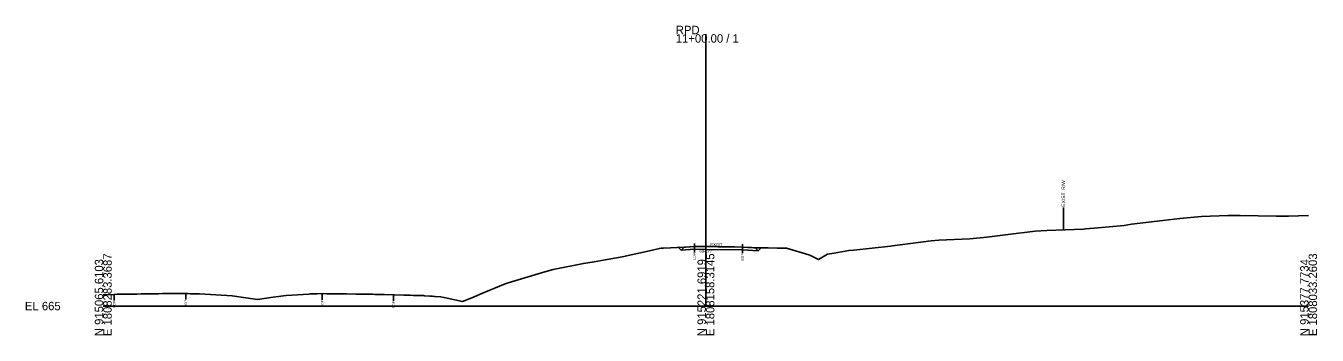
# Model space of a CAD drawing. Extents: x -26 to 403, y -10 to 8517.
# Drawn here: x -25.7 to 402.8, y 1990.3 to 2093.2 of the extents above; entities that cross this region are included whole.
import ezdxf

# ---------------------------------------------------------------- set-up
doc = ezdxf.new("R2010")
doc.units = 0
for name, color, linetype in [('Exist Cross Section Cell', 7, 'Continuous'), ('Exist XS Center Line Elevation Label', 7, 'Continuous'), ('Exist XS Ground Line', 7, 'Continuous'), ('Old_Level_10', 7, 'Continuous'), ('Prop XS Earthwork Shape', 7, 'Continuous'), ('Prop XS EOT Tick Mark', 7, 'Continuous'), ('Prop XS Finish Grade', 7, 'Continuous'), ('Prop XS Finish Grade Paved Shoulder', 7, 'Continuous'), ('Prop XS Finish Grade Pavement', 7, 'Continuous'), ('Prop XS Pvmt Edge Slope', 7, 'Continuous'), ('Prop XS SE Text', 7, 'Continuous'), ('Prop XS Subgrade Earthwork', 7, 'Continuous')]:
    doc.layers.add(name, color=color, linetype=linetype)

msp = doc.modelspace()

# ---------------------------------------------------------------- linework, layer by layer
at = {"layer": 'Exist Cross Section Cell'}
for p, q in [((200, 2000), (200, 2090.35)), ((0, 2000), (200, 2000)), ((200, 2000), (400, 2000))]:
    msp.add_line(p, q, dxfattribs=at)
at = {"layer": 'Exist XS Ground Line'}
msp.add_lwpolyline([(0, 2003.72), (0.56, 2003.73), (1.04, 2003.76), (3.65, 2003.89), (4.59, 2003.91), (6.87, 2003.94), (8.53, 2003.97), (9.38, 2003.98), (10.07, 2003.99), (11.17, 2004), (12.54, 2004.01), (12.95, 2004.01), (13.29, 2004.02), (15.55, 2004.06), (16.51, 2004.08), (18.28, 2004.1), (19.68, 2004.12), (20.49, 2004.13), (22.9, 2004.15), (23.63, 2004.16), (24.53, 2004.17), (26.1, 2004.18), (26.82, 2004.19), (27.4, 2004.2), (28.12, 2004.14), (28.97, 2004.07), (29.31, 2004.07), (31.58, 2004.07), (31.91, 2004.05), (42.81, 2003.35), (47.34, 2002.7), (51.16, 2002.17), (56.37, 2002.91), (60.68, 2003.54), (68.2, 2003.99), (68.7, 2004.02), (69, 2004.02), (70.15, 2004.04), (70.95, 2004.05), (72.68, 2004.12), (74.17, 2004.09), (75.19, 2004.08), (76.5, 2004.07), (76.98, 2004.06), (77.35, 2004.06), (80.74, 2004.03), (83.79, 2003.99), (84.19, 2003.99), (84.74, 2003.98), (86.95, 2003.94), (88.5, 2003.91), (89.42, 2003.9), (90.15, 2003.89), (92.52, 2003.85), (92.98, 2003.84), (93.35, 2003.83), (96.35, 2003.78), (96.68, 2003.77), (99.76, 2003.63), (100.53, 2003.61), (101.86, 2003.57), (102.95, 2003.55), (104.52, 2003.51), (105.58, 2003.49), (106.3, 2003.47), (106.63, 2003.44), (108.38, 2003.31), (109.26, 2003.24), (109.79, 2003.2), (110.14, 2003.18), (111.92, 2003.07), (113.18, 2002.8), (119.23, 2001.47), (122.29, 2002.74), (126.46, 2004.53), (133.33, 2007.36), (133.76, 2007.52), (135.5, 2008.04), (146.58, 2011.42), (149.33, 2012.12), (159.39, 2014.15), (162.87, 2014.71), (165.32, 2015.14), (172.2, 2016.41), (181.31, 2018.39), (184.58, 2019.16), (185.18, 2019.19), (185.87, 2019.22), (192.81, 2019.58), (193.3, 2019.6), (196.17, 2019.81), (197.11, 2019.8), (197.92, 2019.79), (199.09, 2019.78), (200, 2019.77), (200.44, 2019.76), (202.29, 2019.74), (203.4, 2019.74), (203.91, 2019.73), (204.3, 2019.73), (205.48, 2019.71), (206.79, 2019.68), (208.69, 2019.65), (209.63, 2019.64), (212.12, 2019.6), (212.5, 2019.57), (213.92, 2019.47), (215.1, 2019.41), (215.9, 2019.38), (216.36, 2019.37), (220.7, 2019.32), (223.65, 2019.28), (224.68, 2019.27), (226.79, 2019.25), (234.1, 2016.97), (234.7, 2016.77), (237.41, 2015.46), (240.32, 2017.25), (242.5, 2017.63), (247.4, 2018.49), (249.09, 2018.59), (261.28, 2019.94), (261.9, 2020.02), (264.42, 2020.36), (274.71, 2021.71), (277.27, 2021.91), (287.53, 2022.33), (293.26, 2022.91), (300.34, 2023.75), (309.26, 2024.85), (313.16, 2025.1), (325.25, 2025.58), (325.97, 2025.62), (328.88, 2025.92), (338.78, 2026.8), (341.24, 2027.2), (351.6, 2028.48), (357.24, 2029.05), (364.41, 2029.77), (373.23, 2030.12), (377.23, 2030.06), (389.22, 2029.83), (390.04, 2029.9), (393.34, 2029.92), (400, 2030.09)], dxfattribs=at)
at = {"layer": 'Old_Level_10'}
for p, q in [((318.61, 2032.72), (318.61, 2025.31)), ((196.17, 2019.81), (196.17, 2017.76)), ((212.12, 2019.6), (212.12, 2017.55)), ((3.65, 2003.89), (3.65, 2001.84)), ((27.4, 2004.2), (27.4, 2002.15)), ((72.68, 2004.12), (72.68, 2002.07)), ((96.35, 2003.78), (96.35, 2001.73))]:
    msp.add_line(p, q, dxfattribs=at)
at = {"layer": 'Prop XS Earthwork Shape'}
for points in [[(213.92, 2019.47), (215.1, 2019.41), (215.9, 2019.38), (216.36, 2019.37), (218.28, 2019.35), (217.33, 2018.4), (212.09, 2018.69), (199.99, 2018.85), (196.2, 2018.89), (191.8, 2018.58), (190.89, 2019.49), (192.81, 2019.58), (193.3, 2019.6), (196.17, 2019.81), (197.11, 2019.8), (197.92, 2019.79), (199.09, 2019.78), (200, 2019.77), (200.44, 2019.76), (202.29, 2019.74), (203.4, 2019.74), (203.91, 2019.73), (204.3, 2019.73), (205.48, 2019.71), (206.79, 2019.68), (208.69, 2019.65), (209.63, 2019.64), (212.12, 2019.6), (212.5, 2019.57)], [(212.5, 2019.57), (213.92, 2019.47), (215.1, 2019.41), (215.9, 2019.38), (216.36, 2019.37), (218.28, 2019.35), (217.33, 2018.4), (212.09, 2018.69), (199.99, 2018.85), (196.2, 2018.89), (191.8, 2018.58), (190.89, 2019.49), (192.81, 2019.58), (193.3, 2019.6), (196.17, 2019.81), (197.11, 2019.8), (197.92, 2019.79), (199.09, 2019.78), (200, 2019.77), (200.44, 2019.76), (202.29, 2019.74), (203.4, 2019.74), (203.91, 2019.73), (204.3, 2019.73), (205.48, 2019.71), (206.79, 2019.68), (208.69, 2019.65), (209.63, 2019.64), (212.12, 2019.6)]]:
    msp.add_lwpolyline(points, close=True, dxfattribs=at)
at = {"layer": 'Prop XS EOT Tick Mark'}
for p, q in [((196.17, 2019.81), (196.17, 2020.81)), ((212.12, 2019.6), (212.12, 2020.6))]:
    msp.add_line(p, q, dxfattribs=at)
at = {"layer": 'Prop XS Finish Grade'}
for p, q in [((192.81, 2019.58), (190.89, 2019.49)), ((216.36, 2019.37), (218.28, 2019.35))]:
    msp.add_line(p, q, dxfattribs=at)
at = {"layer": 'Prop XS Finish Grade Paved Shoulder'}
for p, q in [((196.17, 2019.81), (192.81, 2019.58)), ((212.12, 2019.6), (216.36, 2019.37))]:
    msp.add_line(p, q, dxfattribs=at)
at = {"layer": 'Prop XS Finish Grade Pavement'}
for p, q in [((196.17, 2019.81), (200, 2019.77)), ((200, 2019.77), (212.12, 2019.6))]:
    msp.add_line(p, q, dxfattribs=at)
at = {"layer": 'Prop XS Pvmt Edge Slope'}
for p, q in [((192.81, 2019.58), (191.8, 2018.58)), ((216.36, 2019.37), (217.33, 2018.4))]:
    msp.add_line(p, q, dxfattribs=at)
at = {"layer": 'Prop XS Subgrade Earthwork'}
for p, q in [((190.89, 2019.49), (191.8, 2018.58)), ((196.2, 2018.89), (191.8, 2018.58)), ((196.2, 2018.89), (199.99, 2018.85)), ((199.99, 2018.85), (212.09, 2018.69)), ((212.09, 2018.69), (217.33, 2018.4)), ((218.28, 2019.35), (217.33, 2018.4))]:
    msp.add_line(p, q, dxfattribs=at)

# ---------------------------------------------------------------- texts
at = {"layer": 'Exist Cross Section Cell'}
for s, p in [('RPD', (190, 2090.35)), ('11+00.00 / 1', (190, 2087.55)), ('EL 665', (-26, 1998.6))]:
    msp.add_text(s, height=2.8, dxfattribs=at).set_placement(p)
for s, p in [('N 915065.6103', (0, 1990)), ('E 1808283.3687', (2.8, 1990)), ('N 915221.6919', (200, 1990)), ('E 1808158.3145', (202.8, 1990)), ('N 915377.7734', (400, 1990)), ('E 1808033.2603', (402.8, 1990))]:
    msp.add_text(s, height=2.8, rotation=90, dxfattribs=at).set_placement(p)
at = {"layer": 'Exist XS Center Line Elevation Label'}
msp.add_text('684.77', height=1, dxfattribs=at).set_placement((197.85, 2017.77))
at = {"layer": 'Old_Level_10'}
for s, height, p in [('EXIST. R/W', 1.181, (319.2, 2033.02)), ('EOP', 0.787, (196.56, 2015.36)), ('EOP', 0.787, (212.51, 2015.15)), ('EOP', 0.787, (4.04, 1999.44)), ('EOP', 0.787, (27.8, 1999.75)), ('EOP', 0.787, (73.07, 1999.67)), ('EOP', 0.787, (96.75, 1999.33))]:
    msp.add_text(s, height=height, rotation=90, dxfattribs=at).set_placement(p)
at = {"layer": 'Prop XS SE Text'}
msp.add_text('EXIST', height=1, rotation=359.7419, dxfattribs=at).set_placement((201.48, 2019.96))

doc.saveas('drawing.dxf')
